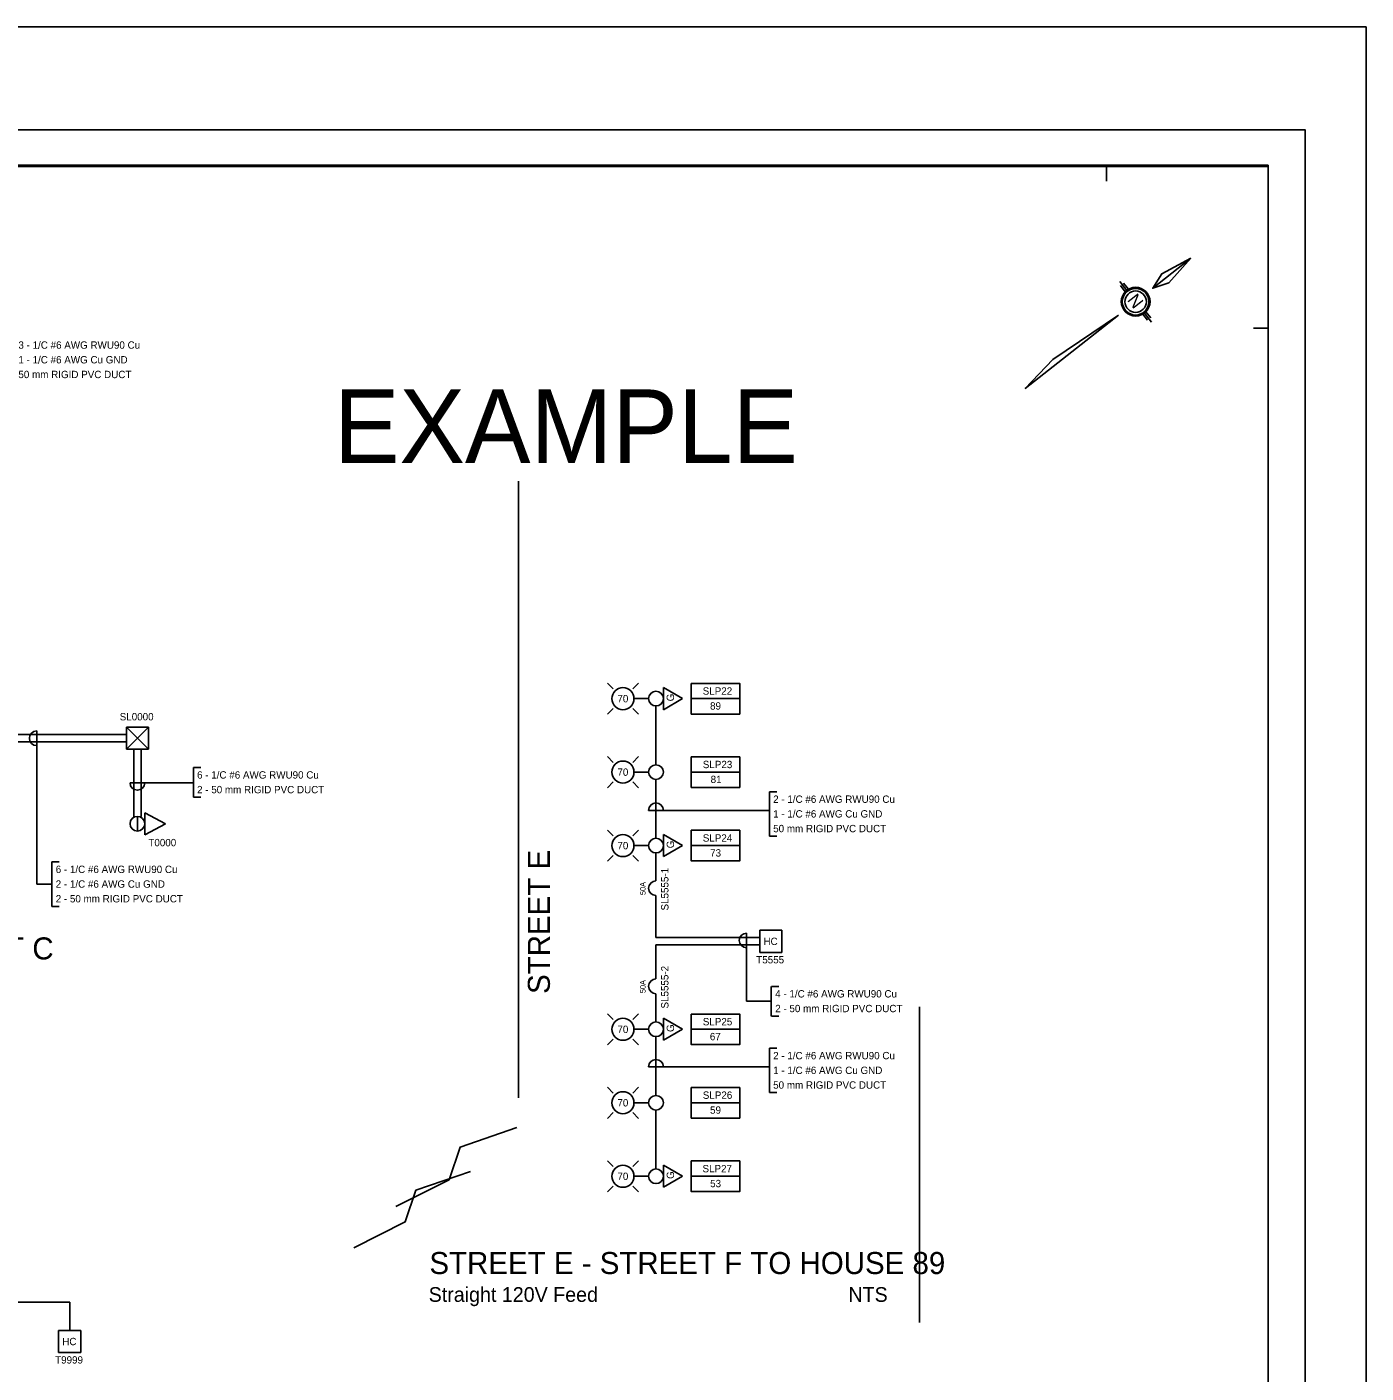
# Model space of a CAD drawing. Extents: x 602909 to 603631, y 4846273 to 4846729.
# Drawn here: x 603194.8 to 603377, y 4846462.4 to 4846645.6 of the extents above; entities that cross this region are included whole.
import ezdxf

# ---------------------------------------------------------------- set-up
doc = ezdxf.new("R2010")
doc.units = 0
for name, color, linetype in [('-PRINT FULLSIZE', 7, 'Continuous'), ('-PRINT HALFSIZE', 7, 'Continuous'), ('ENG_BORDER', 7, 'Continuous'), ('ENG_TITLEBLOCK', 7, 'Continuous'), ('ENG_TX_TITLEBLOCK', 7, 'Continuous'), ('SL - New Duct - OH SL', 7, 'Continuous'), ('SL - Roadway Text', 7, 'Continuous'), ('SL - Wiring Diagram - Level 430', 7, 'Continuous'), ('STL_EXISTING_POLES', 7, 'Continuous'), ('STL_EXISTING_TRANSFORMERS', 7, 'Continuous'), ('STL_FIXTURES', 7, 'Continuous'), ('STL_GND_PLATE', 7, 'Continuous'), ('STL_ID', 7, 'Continuous'), ('STL_POLES', 7, 'Continuous'), ('STL_POWER_SUPPLY', 7, 'Continuous'), ('STL_WIRING', 7, 'Continuous')]:
    doc.layers.add(name, color=color, linetype=linetype)

msp = doc.modelspace()

# ---------------------------------------------------------------- linework, layer by layer
at = {"layer": '-PRINT FULLSIZE'}
msp.add_lwpolyline([(602930, 4846340.65), (603377.03, 4846340.65), (603377.03, 4846645.65), (602930, 4846645.65)], close=True, dxfattribs=at)
at = {"layer": '-PRINT HALFSIZE'}
msp.add_lwpolyline([(602959.8, 4846631.64), (603368.72, 4846631.64), (603368.72, 4846352.64), (602959.8, 4846352.64)], close=True, dxfattribs=at)
at = {"layer": 'ENG_BORDER'}
for p, q in [((603363.72, 4846626.85), (602977.52, 4846626.85)), ((603363.72, 4846357.64), (603363.72, 4846626.85))]:
    msp.add_line(p, q, dxfattribs=at)
msp.add_lwpolyline([(602977.52, 4846357.64), (603363.72, 4846357.64), (603363.72, 4846626.64), (602977.52, 4846626.64)], close=True, dxfattribs=at)
at = {"layer": 'ENG_TITLEBLOCK'}
for p, q in [((603341.72, 4846626.64), (603341.72, 4846624.64)), ((603361.72, 4846604.64), (603363.72, 4846604.64))]:
    msp.add_line(p, q, dxfattribs=at)
at = {"layer": 'SL - New Duct - OH SL'}
msp.add_lwpolyline([(603239.26, 4846479.48), (603246.26, 4846483.02), (603247.71, 4846487.32), (603255.13, 4846489.88)], dxfattribs=at)
msp.add_lwpolyline([(603239.26, 4846479.48), (603246.26, 4846483.02), (603247.71, 4846487.32), (603255.13, 4846489.88)], dxfattribs=at)
msp.add_lwpolyline([(603239.26, 4846479.48), (603246.26, 4846483.02), (603247.71, 4846487.32), (603255.13, 4846489.88)], dxfattribs=at)
at = {"layer": 'SL - Roadway Text'}
for p, q in [((603343.49, 4846611.02), (603344.46, 4846609.79)), ((603344.02, 4846610.76), (603344.67, 4846609.94)), ((603343.61, 4846610.44), (603344.26, 4846609.61)), ((603347.07, 4846606.89), (603347.71, 4846606.07)), ((603346.66, 4846606.57), (603347.3, 4846605.74)), ((603346.87, 4846606.71), (603347.84, 4846605.48))]:
    msp.add_line(p, q, dxfattribs=at)
for points in [[(603353.18, 4846614.16), (603349.23, 4846612.05), (603347.99, 4846610.08)], [(603353.18, 4846614.16), (603347.99, 4846610.08), (603350.2, 4846610.82)], [(603343.34, 4846606.43), (603334.39, 4846600.38), (603330.63, 4846596.44)]]:
    msp.add_lwpolyline(points, close=True, dxfattribs=at)
for radius in [1.96, 1.81, 1.46]:
    msp.add_circle((603345.66, 4846608.25), radius, dxfattribs=at)
at = {"layer": 'SL - Wiring Diagram - Level 430'}
for p, q in [((603261.66, 4846499.91), (603261.66, 4846583.82)), ((603261.66, 4846499.91), (603261.66, 4846582.67)), ((603285.19, 4846554.23), (603291.79, 4846554.23)), ((603209.8, 4846548.84), (603209.8, 4846548.84)), ((603316.25, 4846469.34), (603316.25, 4846512.29)), ((603190.35, 4846472.08), (603198.35, 4846472.08))]:
    msp.add_line(p, q, dxfattribs=at)
for points in [[(603261.66, 4846575.05), (603261.66, 4846583.82)], [(603244.99, 4846485.1), (603252.25, 4846488.76), (603253.75, 4846493.21), (603261.43, 4846495.87)], [(603244.99, 4846485.1), (603252.25, 4846488.76), (603253.75, 4846493.21), (603261.43, 4846495.87)], [(603244.99, 4846485.1), (603252.25, 4846488.76), (603253.75, 4846493.21), (603261.43, 4846495.87)], [(603190.35, 4846472.08), (603198.35, 4846472.08)]]:
    msp.add_lwpolyline(points, dxfattribs=at)
msp.add_lwpolyline([(603285.19, 4846556.31), (603291.79, 4846556.31), (603291.79, 4846552.14), (603285.19, 4846552.14)], close=True, dxfattribs=at)
at = {"layer": 'STL_EXISTING_POLES'}
for q in [(603209.8, 4846536.21), (603209.8, 4846538.21)]:
    msp.add_line((603209.8, 4846538.21), q, dxfattribs=at)
for start, end in [(90, 270), (270, 90)]:
    msp.add_arc((603209.8, 4846537.21), 1, start, end, dxfattribs=at)
at = {"layer": 'STL_EXISTING_TRANSFORMERS'}
for p, q in [((603210.8, 4846535.71), (603210.8, 4846538.71)), ((603213.63, 4846537.21), (603210.8, 4846538.71)), ((603213.63, 4846537.21), (603210.8, 4846535.71)), ((603294.52, 4846519.7), (603294.52, 4846522.7)), ((603294.52, 4846522.7), (603297.52, 4846522.7)), ((603296.02, 4846522.7), (603297.52, 4846522.7)), ((603297.52, 4846522.7), (603297.51, 4846519.7)), ((603297.51, 4846519.7), (603294.52, 4846519.7)), ((603199.08, 4846465.24), (603199.08, 4846468.24)), ((603199.08, 4846468.24), (603202.08, 4846468.24)), ((603200.58, 4846468.24), (603202.08, 4846468.24)), ((603202.08, 4846468.24), (603202.08, 4846465.24)), ((603202.08, 4846465.24), (603199.08, 4846465.24))]:
    msp.add_line(p, q, dxfattribs=at)
at = {"layer": 'STL_FIXTURES'}
for p, q in [((603274.56, 4846555.55), (603273.76, 4846556.35)), ((603277.21, 4846555.55), (603278, 4846556.35)), ((603277.38, 4846554.23), (603279.38, 4846554.23)), ((603274.56, 4846552.9), (603273.76, 4846552.11)), ((603277.21, 4846552.9), (603278, 4846552.1)), ((603274.56, 4846545.55), (603273.76, 4846546.35)), ((603277.21, 4846545.55), (603278, 4846546.35)), ((603274.56, 4846542.9), (603273.76, 4846542.11)), ((603277.21, 4846542.9), (603278, 4846542.1)), ((603277.38, 4846544.23), (603279.38, 4846544.23)), ((603274.56, 4846535.55), (603273.76, 4846536.35)), ((603277.21, 4846535.55), (603278, 4846536.35)), ((603277.38, 4846534.23), (603279.38, 4846534.23)), ((603274.56, 4846532.9), (603273.76, 4846532.11)), ((603277.21, 4846532.9), (603278, 4846532.1)), ((603274.56, 4846510.55), (603273.76, 4846511.35)), ((603277.21, 4846510.55), (603278, 4846511.35)), ((603277.38, 4846509.23), (603279.38, 4846509.23)), ((603274.56, 4846507.9), (603273.76, 4846507.11)), ((603277.21, 4846507.9), (603278, 4846507.1)), ((603274.56, 4846500.55), (603273.76, 4846501.35)), ((603277.21, 4846500.55), (603278, 4846501.35)), ((603277.38, 4846499.23), (603279.38, 4846499.23)), ((603274.56, 4846497.9), (603273.76, 4846497.11)), ((603277.21, 4846497.9), (603278, 4846497.1)), ((603274.56, 4846490.55), (603273.76, 4846491.35)), ((603277.21, 4846490.55), (603278, 4846491.35)), ((603274.56, 4846487.9), (603273.76, 4846487.11)), ((603277.21, 4846487.9), (603278, 4846487.1)), ((603277.38, 4846489.23), (603279.38, 4846489.23))]:
    msp.add_line(p, q, dxfattribs=at)
for centre in [(603275.88, 4846554.23), (603275.88, 4846544.23), (603275.88, 4846534.23), (603275.88, 4846509.23), (603275.88, 4846499.23), (603275.88, 4846489.23)]:
    msp.add_circle(centre, 1.5, dxfattribs=at)
at = {"layer": 'STL_GND_PLATE'}
for p, q in [((603281.38, 4846555.73), (603283.98, 4846554.23)), ((603281.38, 4846552.73), (603281.38, 4846555.73)), ((603283.98, 4846554.23), (603281.38, 4846552.73)), ((603281.38, 4846535.73), (603283.98, 4846534.23)), ((603281.38, 4846532.73), (603281.38, 4846535.73)), ((603283.98, 4846534.23), (603281.38, 4846532.73)), ((603281.38, 4846510.73), (603283.98, 4846509.23)), ((603281.38, 4846507.73), (603281.38, 4846510.73)), ((603283.98, 4846509.23), (603281.38, 4846507.73)), ((603281.38, 4846490.73), (603283.98, 4846489.23)), ((603281.38, 4846487.73), (603281.38, 4846490.73)), ((603283.98, 4846489.23), (603281.38, 4846487.73))]:
    msp.add_line(p, q, dxfattribs=at)
at = {"layer": 'STL_ID'}
for p, q in [((603285.19, 4846544.23), (603291.79, 4846544.23)), ((603285.19, 4846534.23), (603291.79, 4846534.23)), ((603285.19, 4846509.23), (603291.79, 4846509.23)), ((603285.19, 4846499.23), (603291.79, 4846499.23)), ((603285.19, 4846489.23), (603291.79, 4846489.23))]:
    msp.add_line(p, q, dxfattribs=at)
for points in [[(603285.19, 4846546.31), (603291.79, 4846546.31), (603291.79, 4846542.14), (603285.19, 4846542.14)], [(603285.19, 4846536.31), (603291.79, 4846536.31), (603291.79, 4846532.14), (603285.19, 4846532.14)], [(603285.19, 4846511.31), (603291.79, 4846511.31), (603291.79, 4846507.14), (603285.19, 4846507.14)], [(603285.19, 4846501.31), (603291.79, 4846501.31), (603291.79, 4846497.14), (603285.19, 4846497.14)], [(603285.19, 4846491.31), (603291.79, 4846491.31), (603291.79, 4846487.14), (603285.19, 4846487.14)]]:
    msp.add_lwpolyline(points, close=True, dxfattribs=at)
at = {"layer": 'STL_POLES'}
for centre in [(603280.38, 4846554.23), (603280.38, 4846544.23), (603280.38, 4846534.23), (603280.38, 4846509.23), (603280.38, 4846499.23), (603280.38, 4846489.23)]:
    msp.add_circle(centre, 1, dxfattribs=at)
at = {"layer": 'STL_POWER_SUPPLY'}
for p, q in [((603208.3, 4846547.34), (603208.3, 4846550.34)), ((603208.3, 4846550.34), (603211.3, 4846550.34)), ((603208.3, 4846550.34), (603211.3, 4846547.34)), ((603211.3, 4846550.34), (603208.3, 4846547.34)), ((603209.8, 4846550.34), (603211.3, 4846550.34)), ((603211.3, 4846550.34), (603211.3, 4846547.34)), ((603211.3, 4846547.34), (603208.3, 4846547.34)), ((603280.38, 4846529.43), (603280.38, 4846530.43)), ((603280.38, 4846527.43), (603280.38, 4846526.43)), ((603280.38, 4846516.08), (603280.38, 4846517.08)), ((603280.38, 4846514.08), (603280.38, 4846513.08))]:
    msp.add_line(p, q, dxfattribs=at)
for centre in [(603280.38, 4846528.43), (603280.38, 4846515.08)]:
    msp.add_arc(centre, 1, 90, 270, dxfattribs=at)
at = {"layer": 'STL_WIRING'}
for p, q in [((603280.38, 4846545.23), (603280.38, 4846553.23)), ((603208.3, 4846548.34), (603186.78, 4846548.34)), ((603190.64, 4846549.34), (603208.3, 4846549.34)), ((603196.1, 4846549.84), (603196.1, 4846547.84)), ((603196.1, 4846547.84), (603196.1, 4846528.98)), ((603209.3, 4846547.34), (603209.3, 4846538.21)), ((603210.3, 4846538.21), (603210.3, 4846547.34)), ((603217.41, 4846544.85), (603218.41, 4846544.85)), ((603208.8, 4846542.77), (603210.8, 4846542.77)), ((603209.3, 4846542.77), (603210.3, 4846542.77)), ((603210.8, 4846542.77), (603217.41, 4846542.77)), ((603280.38, 4846535.23), (603280.38, 4846543.23)), ((603295.83, 4846541.55), (603296.83, 4846541.55)), ((603217.41, 4846540.81), (603218.41, 4846540.81)), ((603279.38, 4846539.03), (603295.83, 4846539.03)), ((603295.83, 4846535.52), (603296.83, 4846535.52)), ((603198.16, 4846532), (603199.16, 4846532)), ((603280.38, 4846529.43), (603280.38, 4846533.23)), ((603196.1, 4846528.98), (603198.16, 4846528.98)), ((603280.38, 4846521.73), (603280.38, 4846527.43)), ((603198.16, 4846525.96), (603199.16, 4846525.96)), ((603280.38, 4846521.73), (603294.52, 4846521.73)), ((603292.71, 4846522.32), (603292.71, 4846520.32)), ((603280.38, 4846520.73), (603294.52, 4846520.73)), ((603280.38, 4846516.08), (603280.38, 4846520.73)), ((603292.71, 4846520.32), (603292.71, 4846513.05)), ((603280.38, 4846510.23), (603280.38, 4846514.08)), ((603296.11, 4846515.06), (603297.11, 4846515.06)), ((603292.71, 4846513.05), (603296.09, 4846513.05)), ((603296.09, 4846511.03), (603297.09, 4846511.03)), ((603280.38, 4846500.23), (603280.38, 4846508.23)), ((603295.83, 4846506.65), (603296.83, 4846506.65)), ((603279.38, 4846504.13), (603295.83, 4846504.13)), ((603295.83, 4846500.62), (603296.83, 4846500.62)), ((603280.38, 4846490.23), (603280.38, 4846498.23)), ((603190.21, 4846472.08), (603200.58, 4846472.08)), ((603200.58, 4846472.08), (603200.58, 4846468.24))]:
    msp.add_line(p, q, dxfattribs=at)
for points in [[(603217.41, 4846540.81), (603217.41, 4846544.85)], [(603295.81, 4846535.52), (603295.81, 4846541.55)], [(603198.16, 4846525.96), (603198.16, 4846532)], [(603296.07, 4846511.03), (603296.07, 4846515.06)], [(603295.81, 4846500.62), (603295.81, 4846506.65)]]:
    msp.add_lwpolyline(points, dxfattribs=at)
for centre, start, end in [((603196.1, 4846548.84), 90, 270), ((603209.8, 4846542.77), 180, 360), ((603280.38, 4846539.03), 0, 180), ((603292.71, 4846521.32), 90, 270), ((603280.38, 4846504.13), 0, 180)]:
    msp.add_arc(centre, 1, start, end, dxfattribs=at)

# ---------------------------------------------------------------- texts
at = {"layer": 'ENG_TX_TITLEBLOCK'}
for s, height, p in [('EXAMPLE', 10, (603236.54, 4846586.31)), ('STREET A - STREET B TO STREET C', 3, (603127.96, 4846518.74)), ('STREET E - STREET F TO HOUSE 89', 3, (603249.54, 4846475.92)), ('Straight 120V Feed', 2, (603249.44, 4846472.14)), ('NTS', 2, (603306.57, 4846472.14))]:
    msp.add_text(s, height=height, dxfattribs=at).set_placement(p)
msp.add_text('STREET E', height=3, rotation=90, dxfattribs=at).set_placement((603265.94, 4846514.04))
at = {"layer": 'SL - Roadway Text'}
msp.add_text('N', height=1.73, rotation=308.1708, dxfattribs=at).set_placement((603344.45, 4846608.46))
at = {"layer": 'SL - Wiring Diagram - Level 430'}
for s, p in [('SLP22', (603286.74, 4846554.77)), ('89', (603287.74, 4846552.74))]:
    msp.add_text(s, height=1, dxfattribs=at).set_placement(p)
at = {"layer": 'STL_EXISTING_TRANSFORMERS'}
for s, p in [('HC', (603295.01, 4846520.7)), ('T5555', (603294.03, 4846518.2)), ('HC', (603199.57, 4846466.24)), ('T9999', (603198.6, 4846463.74))]:
    msp.add_text(s, height=1, rotation=359.9999, dxfattribs=at).set_placement(p)
at = {"layer": 'STL_GND_PLATE'}
for p in [(603282.84, 4846553.86), (603282.84, 4846533.86), (603282.84, 4846508.86), (603282.84, 4846488.86)]:
    msp.add_text('G', height=1, rotation=89.9999, dxfattribs=at).set_placement(p)
at = {"layer": 'STL_ID'}
for s, p in [('3 - 1/C #6 AWG RWU90 Cu', (603193.6, 4846601.85)), ('1 - 1/C #6 AWG Cu GND', (603193.6, 4846599.85)), ('50 mm RIGID PVC DUCT', (603193.6, 4846597.85)), ('70', (603275.13, 4846553.73)), ('70', (603275.13, 4846543.73)), ('SLP23', (603286.75, 4846544.77)), ('6 - 1/C #6 AWG RWU90 Cu', (603217.92, 4846543.35)), ('81', (603287.82, 4846542.74)), ('2 - 50 mm RIGID PVC DUCT', (603217.92, 4846541.35)), ('2 - 1/C #6 AWG RWU90 Cu', (603296.33, 4846540.05)), ('1 - 1/C #6 AWG Cu GND', (603296.33, 4846538.05)), ('SLP24', (603286.75, 4846534.77)), ('50 mm RIGID PVC DUCT', (603296.33, 4846536.05)), ('70', (603275.13, 4846533.73)), ('73', (603287.75, 4846532.74)), ('6 - 1/C #6 AWG RWU90 Cu', (603198.68, 4846530.5)), ('2 - 1/C #6 AWG Cu GND', (603198.68, 4846528.5)), ('2 - 50 mm RIGID PVC DUCT', (603198.68, 4846526.5)), ('4 - 1/C #6 AWG RWU90 Cu', (603296.61, 4846513.56)), ('2 - 50 mm RIGID PVC DUCT', (603296.61, 4846511.56)), ('SLP25', (603286.75, 4846509.77)), ('70', (603275.13, 4846508.73)), ('67', (603287.71, 4846507.74)), ('2 - 1/C #6 AWG RWU90 Cu', (603296.33, 4846505.15)), ('1 - 1/C #6 AWG Cu GND', (603296.33, 4846503.15)), ('SLP26', (603286.75, 4846499.77)), ('50 mm RIGID PVC DUCT', (603296.33, 4846501.15)), ('70', (603275.13, 4846498.73)), ('59', (603287.74, 4846497.74)), ('70', (603275.13, 4846488.73)), ('SLP27', (603286.71, 4846489.77)), ('53', (603287.75, 4846487.74))]:
    msp.add_text(s, height=1, dxfattribs=at).set_placement(p)
msp.add_text('T0000', height=1, rotation=359.9999, dxfattribs=at).set_placement((603211.29, 4846534.14))
at = {"layer": 'STL_POWER_SUPPLY'}
for s, height, rotation, p in [('SL0000', 1, 359.9999, (603207.39, 4846551.27)), ('SL5555-1', 1, 89.9999, (603282.08, 4846525.4)), ('50A', 0.75, 90, (603278.96, 4846527.5)), ('SL5555-2', 1, 89.9999, (603282.08, 4846512.06)), ('50A', 0.75, 90, (603278.96, 4846514.15))]:
    msp.add_text(s, height=height, rotation=rotation, dxfattribs=at).set_placement(p)

doc.saveas('drawing.dxf')
